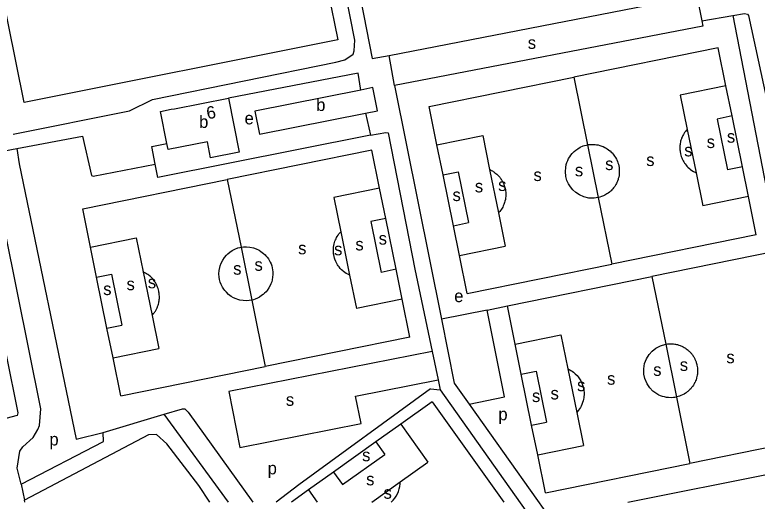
# Model space of a CAD drawing. Extents: x 160204 to 161526, y 379528 to 381793.
# Drawn here: x 160863 to 161102.1, y 380224.6 to 380381.3 of the extents above; entities that cross this region are included whole.
import ezdxf

# ---------------------------------------------------------------- set-up
doc = ezdxf.new("R2010")
doc.units = 0
for name, color, linetype in [('BLT_Basislijn', 7, 'Continuous'), ('BLT_Bebouwing', 7, 'Continuous'), ('BLT_Centroide', 7, 'Continuous'), ('BLT_Huisnummer', 7, 'Continuous')]:
    doc.layers.add(name, color=color, linetype=linetype)

msp = doc.modelspace()

# ---------------------------------------------------------------- linework, layer by layer
at = {"layer": 'BLT_Basislijn'}
for p, q in [((161084.23, 380379.36), (161094.28, 380381.12)), ((161094.28, 380381.12), (161108.89, 380305.3)), ((161089.54, 380370.73), (161042.99, 380361.26)), ((161092.04, 380358.42), (161089.54, 380370.73)), ((160985.22, 380358.5), (160983.57, 380368.26)), ((160996.44, 380351.79), (161042.99, 380361.26)), ((161042.99, 380361.26), (161047.43, 380339.43)), ((160985.22, 380358.5), (161000.38, 380283.25)), ((161092.04, 380358.42), (161077.31, 380355.42)), ((161094.02, 380348.73), (161092.04, 380358.42)), ((161077.31, 380355.42), (161079.55, 380344.42)), ((160998.94, 380339.48), (160996.44, 380351.79)), ((160975.88, 380349.59), (160977.58, 380342.53)), ((161094.02, 380348.73), (161089.2, 380347.75)), ((161097.35, 380332.34), (161094.02, 380348.73)), ((161089.2, 380347.75), (161092.54, 380331.36)), ((161079.55, 380344.42), (161082.4, 380330.42)), ((160998.94, 380339.48), (161013.68, 380342.48)), ((161013.68, 380342.48), (161015.91, 380331.48)), ((161000.92, 380329.78), (160998.94, 380339.48)), ((161047.43, 380339.43), (161050.89, 380322.43)), ((160977.95, 380337.73), (160931.4, 380328.25)), ((160980.46, 380325.42), (160977.95, 380337.73)), ((161097.35, 380332.34), (161092.54, 380331.36)), ((161099.31, 380322.74), (161097.35, 380332.34)), ((161000.92, 380329.78), (161005.73, 380330.76)), ((161004.25, 380313.39), (161000.92, 380329.78)), ((161005.73, 380330.76), (161009.07, 380314.37)), ((161015.91, 380331.48), (161018.76, 380317.48)), ((161082.4, 380330.42), (161084.57, 380319.74)), ((160884.85, 380318.78), (160931.4, 380328.25)), ((160931.4, 380328.25), (160935.83, 380306.46)), ((160980.46, 380325.42), (160965.72, 380322.42)), ((160982.43, 380315.72), (160980.46, 380325.42)), ((160965.72, 380322.42), (160967.96, 380311.42)), ((161050.89, 380322.43), (161055.25, 380301.01)), ((161099.31, 380322.74), (161084.57, 380319.74)), ((161101.8, 380310.49), (161099.31, 380322.74)), ((160887.35, 380306.47), (160884.85, 380318.78)), ((161018.76, 380317.48), (161020.94, 380306.79)), ((160982.43, 380315.72), (160977.61, 380314.74)), ((160985.76, 380299.33), (160982.43, 380315.72)), ((160977.61, 380314.74), (160980.95, 380298.35)), ((161004.25, 380313.39), (161009.07, 380314.37)), ((161006.21, 380303.79), (161004.25, 380313.39)), ((160967.96, 380311.42), (160970.8, 380297.45)), ((161101.8, 380310.49), (161055.25, 380301.01)), ((160887.35, 380306.47), (160902.09, 380309.47)), ((160902.09, 380309.47), (160904.31, 380298.53)), ((160889.33, 380296.78), (160887.35, 380306.47)), ((160932.24, 380304.88), (160933, 380305.39)), ((160933, 380305.39), (160933.89, 380305.85)), ((160933.89, 380305.85), (160934.84, 380306.2)), ((160934.84, 380306.2), (160935.52, 380306.37)), ((160935.52, 380306.37), (160935.83, 380306.46)), ((160935.83, 380306.46), (160936.65, 380306.55)), ((160935.83, 380306.46), (160939.3, 380289.41)), ((160936.04, 380306.48), (160936.13, 380306.49)), ((160936.65, 380306.55), (160937.61, 380306.58)), ((160937.61, 380306.58), (160938.71, 380306.49)), ((160938.71, 380306.49), (160939.84, 380306.24)), ((160939.84, 380306.24), (160940.7, 380305.95)), ((160940.7, 380305.95), (160941.73, 380305.45)), ((160941.73, 380305.45), (160942.26, 380305.11)), ((161006.21, 380303.79), (161020.94, 380306.79)), ((161108.89, 380305.3), (161068.19, 380297.01)), ((160929.94, 380302.31), (160930.48, 380303.1)), ((160930.48, 380303.1), (160931.12, 380303.87)), ((160931.12, 380303.87), (160931.6, 380304.35)), ((160931.6, 380304.35), (160932.24, 380304.88)), ((160942.26, 380305.11), (160943.13, 380304.45)), ((160943.13, 380304.45), (160943.58, 380304.01)), ((160943.58, 380304.01), (160943.87, 380303.71)), ((160943.87, 380303.71), (160944.27, 380303.24)), ((160944.27, 380303.24), (160944.64, 380302.72)), ((161008.7, 380291.54), (161006.21, 380303.79)), ((160929.11, 380300.4), (160929.43, 380301.31)), ((160929.43, 380301.31), (160929.94, 380302.31)), ((160944.64, 380302.72), (160944.93, 380302.24)), ((160944.93, 380302.24), (160945.24, 380301.66)), ((160945.24, 380301.66), (160945.51, 380301.06)), ((160945.51, 380301.06), (160945.71, 380300.48)), ((161008.7, 380291.54), (161055.25, 380301.01)), ((160904.31, 380298.53), (160907.17, 380284.48)), ((160928.73, 380297.84), (160928.81, 380298.98)), ((160928.81, 380298.98), (160928.96, 380299.89)), ((160928.96, 380299.89), (160929.11, 380300.4)), ((160945.71, 380300.48), (160945.9, 380299.77)), ((160945.9, 380299.77), (160946.02, 380299.11)), ((160946.02, 380299.11), (160946.08, 380298.52)), ((160946.08, 380298.52), (160946.1, 380297.63)), ((160985.76, 380299.33), (160980.95, 380298.35)), ((160987.72, 380289.73), (160985.76, 380299.33)), ((160889.33, 380296.78), (160894.14, 380297.76)), ((160892.66, 380280.39), (160889.33, 380296.78)), ((160894.14, 380297.76), (160897.48, 380281.37)), ((160928.8, 380296.79), (160928.73, 380297.84)), ((160928.93, 380296.06), (160928.8, 380296.79)), ((160929.17, 380295.2), (160928.93, 380296.06)), ((160945.88, 380295.95), (160945.72, 380295.35)), ((160946.02, 380296.76), (160945.88, 380295.95)), ((160946.1, 380297.63), (160946.02, 380296.76)), ((160970.8, 380297.45), (160972.98, 380286.73)), ((161021.64, 380287.54), (161068.19, 380297.01)), ((161068.19, 380297.01), (161072.63, 380275.19)), ((160929.48, 380294.39), (160929.17, 380295.2)), ((160929.89, 380293.59), (160929.48, 380294.39)), ((160930.27, 380292.96), (160929.89, 380293.59)), ((160944.81, 380293.34), (160944.24, 380292.51)), ((160945.22, 380294.08), (160944.81, 380293.34)), ((160945.48, 380294.64), (160945.22, 380294.08)), ((160945.72, 380295.35), (160945.48, 380294.64)), ((160930.62, 380292.5), (160930.27, 380292.96)), ((160931.13, 380291.93), (160930.62, 380292.5)), ((160931.84, 380291.23), (160931.13, 380291.93)), ((160932.67, 380290.62), (160931.84, 380291.23)), ((160943, 380291.24), (160942.48, 380290.85)), ((160943.44, 380291.66), (160943, 380291.24)), ((160943.9, 380292.11), (160943.44, 380291.66)), ((160944.24, 380292.51), (160943.9, 380292.11)), ((160933.45, 380290.18), (160932.67, 380290.62)), ((160934.24, 380289.82), (160933.45, 380290.18)), ((160934.83, 380289.61), (160934.24, 380289.82)), ((160935.5, 380289.42), (160934.83, 380289.61)), ((160936.49, 380289.24), (160935.5, 380289.42)), ((160937.46, 380289.21), (160936.49, 380289.24)), ((160938.42, 380289.27), (160937.46, 380289.21)), ((160939.3, 380289.41), (160938.42, 380289.27)), ((160939.82, 380289.55), (160939.3, 380289.41)), ((160939.3, 380289.41), (160943.66, 380268.01)), ((160940.43, 380289.76), (160939.82, 380289.55)), ((160941.09, 380290.03), (160940.43, 380289.76)), ((160941.74, 380290.37), (160941.09, 380290.03)), ((160942.48, 380290.85), (160941.74, 380290.37)), ((160987.72, 380289.73), (160972.98, 380286.73)), ((160990.21, 380277.48), (160987.72, 380289.73)), ((161015.11, 380286.22), (161000.38, 380283.25)), ((161015.11, 380286.22), (161021.64, 380287.54)), ((161024.14, 380275.23), (161021.64, 380287.54)), ((160907.17, 380284.48), (160909.35, 380273.78)), ((160892.66, 380280.39), (160897.48, 380281.37)), ((161000.38, 380283.25), (161004.52, 380262.7)), ((160894.62, 380270.78), (160892.66, 380280.39)), ((160990.21, 380277.48), (160943.66, 380268.01)), ((161024.14, 380275.23), (161038.88, 380278.23)), ((161038.88, 380278.23), (161041.12, 380267.24)), ((161026.12, 380265.54), (161024.14, 380275.23)), ((161072.63, 380275.19), (161076.09, 380258.18)), ((160894.62, 380270.78), (160909.35, 380273.78)), ((160897.11, 380258.54), (160894.62, 380270.78)), ((160897.11, 380258.54), (160943.66, 380268.01)), ((161041.12, 380267.24), (161043.96, 380253.24)), ((161026.12, 380265.54), (161030.93, 380266.52)), ((161029.45, 380249.15), (161026.12, 380265.54)), ((161030.93, 380266.52), (161034.27, 380250.13)), ((161004.52, 380262.7), (161009.34, 380255.9)), ((160996.92, 380260.88), (160999.97, 380260.47)), ((160999.97, 380260.47), (161053.56, 380184.93)), ((161076.09, 380258.18), (161080.45, 380236.77)), ((160997.43, 380256.65), (160987.26, 380249.4)), ((160997.43, 380256.65), (161020.47, 380224.32)), ((161009.34, 380255.9), (161057.78, 380187.62)), ((160891.4, 380246.76), (160911.04, 380252.7)), ((160931.83, 380224.32), (160911.04, 380252.7)), ((161043.96, 380253.24), (161046.14, 380242.54)), ((160987.26, 380249.4), (160979.27, 380243.71)), ((160987.26, 380249.4), (160995.98, 380237.15)), ((161029.45, 380249.15), (161034.27, 380250.13)), ((161031.41, 380239.55), (161029.45, 380249.15)), ((161127, 380246.24), (161080.45, 380236.77)), ((160979.27, 380243.71), (160965.65, 380234)), ((160979.27, 380243.71), (160982.13, 380239.71)), ((161031.41, 380239.55), (161046.14, 380242.54)), ((160968.51, 380230), (160982.13, 380239.71)), ((161033.9, 380227.3), (161031.41, 380239.55)), ((161060.45, 380224.32), (161136.14, 380239.36)), ((160987.1, 380230.82), (160995.98, 380237.15)), ((161033.9, 380227.3), (161080.45, 380236.77)), ((160965.65, 380234), (160957.6, 380228.26)), ((160965.65, 380234), (160968.51, 380230)), ((160865.02, 380230.15), (160866.11, 380224.96)), ((160977.98, 380224.32), (160987.1, 380230.82)), ((160957.6, 380228.26), (160952.08, 380224.32)), ((160957.6, 380228.26), (160960.4, 380224.32)), ((160866.24, 380224.32), (160866.11, 380224.96))]:
    msp.add_line(p, q, dxfattribs=at)
for points in [[(160862.4, 380342.89), (160899.88, 380350.43), (160907.33, 380354.09), (160966.36, 380366.04), (160969.23, 380366.8), (160971.97, 380368.63), (160972.33, 380369.68), (160972.48, 380373.18), (160947.15, 380501.94), (160947.23, 380502.7), (160955.13, 380504.39), (160952.23, 380519.45)], [(160961.41, 380463.33), (160959.6, 380462.97), (160960.64, 380456.41), (160978.09, 380367.21)], [(160855.42, 380404.86), (160853.74, 380413.3), (160853.25, 380417.58), (160953.85, 380437.27), (160960.59, 380405.79), (160960.75, 380403.91), (160967.05, 380373.22), (160866.02, 380353.12), (160855.42, 380404.86)], [(161079.12, 380386.74), (161082.68, 380387.43), (161084.23, 380379.36)], [(160983.57, 380368.26), (161074.21, 380385.79)], [(161094.28, 380381.12), (161098, 380381.77), (161099.02, 380381.54), (161099.3, 380381.07), (161112.98, 380318.06), (161113.11, 380317.77), (161120.31, 380318.94), (161121.12, 380317.68), (161126.85, 380288.91), (161136.14, 380239.36)], [(161084.23, 380379.36), (161084.56, 380377.64), (160985.22, 380358.5)], [(160978.09, 380367.21), (160983.57, 380368.26)], [(160974.39, 380357.08), (160973.55, 380362.55), (160931.8, 380354.52)], [(161079.55, 380344.42), (161079.5, 380344.38), (161079.34, 380344.2), (161079.17, 380344), (161078.96, 380343.73), (161078.71, 380343.39), (161078.48, 380343.02), (161078.33, 380342.76), (161078.16, 380342.47), (161078.05, 380342.23), (161077.91, 380341.95), (161077.77, 380341.6), (161077.67, 380341.33), (161077.55, 380340.94), (161077.45, 380340.58), (161077.37, 380340.24), (161077.31, 380339.89), (161077.25, 380339.51), (161077.22, 380339.2), (161077.19, 380338.91), (161077.19, 380338.66), (161077.18, 380338.23), (161077.21, 380337.81), (161077.24, 380337.46), (161077.28, 380337.14), (161077.36, 380336.69), (161077.4, 380336.51), (161077.5, 380336.12), (161077.62, 380335.71), (161077.69, 380335.51), (161077.78, 380335.25), (161077.91, 380334.96), (161078.12, 380334.51), (161078.24, 380334.29), (161078.43, 380333.94), (161078.68, 380333.54), (161078.88, 380333.26), (161079.17, 380332.89), (161079.49, 380332.52), (161079.74, 380332.26), (161080.38, 380331.68), (161080.67, 380331.45), (161081.06, 380331.17), (161081.57, 380330.85), (161082.07, 380330.59), (161082.4, 380330.42)], [(160863.57, 380338.29), (160884.75, 380342.19), (160887.72, 380329.58), (160888.26, 380329.29), (160908.2, 380333.23)], [(160977.58, 380342.53), (160909.05, 380328.91), (160908.2, 380333.23)], [(160977.58, 380342.53), (160982.5, 380343.43), (160983.2, 380343.31), (160991.86, 380299.42), (160997.4, 380272.83)], [(160908.2, 380333.23), (160907.07, 380338.9), (160911.95, 380339.89)], [(161050.89, 380322.43), (161049.64, 380322.24), (161047.82, 380322.3), (161046.21, 380322.69), (161044.84, 380323.29), (161043.68, 380324.05), (161042.72, 380324.92), (161041.93, 380325.88), (161041.34, 380326.83), (161040.83, 380327.99), (161040.49, 380329.26), (161040.33, 380330.83), (161040.41, 380332.09), (161040.6, 380333.05), (161040.8, 380333.73), (161041.07, 380334.4), (161041.34, 380334.98), (161041.7, 380335.59), (161042.09, 380336.14), (161042.52, 380336.67), (161043.1, 380337.26), (161043.63, 380337.71), (161044.3, 380338.19), (161045.13, 380338.67), (161046.04, 380339.06)], [(161046.04, 380339.06), (161046.49, 380339.21), (161047.08, 380339.36), (161047.43, 380339.43)], [(161047.43, 380339.43), (161047.8, 380339.5), (161048.19, 380339.55), (161048.73, 380339.58), (161049.29, 380339.58), (161049.95, 380339.53), (161050.33, 380339.48), (161050.86, 380339.39), (161051.41, 380339.25), (161052.01, 380339.05), (161052.5, 380338.85), (161052.98, 380338.62), (161053.5, 380338.34), (161053.8, 380338.14), (161054.24, 380337.84), (161054.59, 380337.55), (161054.71, 380337.46), (161055.09, 380337.1), (161055.37, 380336.81), (161055.69, 380336.44), (161055.96, 380336.1), (161056.19, 380335.78), (161056.44, 380335.4), (161056.75, 380334.83), (161056.88, 380334.57), (161057.09, 380334.07), (161057.26, 380333.62), (161057.38, 380333.21), (161057.51, 380332.69), (161057.6, 380332.17), (161057.65, 380331.79), (161057.67, 380331.46), (161057.69, 380330.94), (161057.68, 380330.45), (161057.65, 380330.09), (161057.59, 380329.56), (161057.49, 380329.04), (161057.37, 380328.55), (161057.29, 380328.28), (161057.1, 380327.74), (161056.92, 380327.31), (161056.77, 380327.02), (161056.58, 380326.64), (161056.33, 380326.24), (161056.2, 380326.04), (161056.04, 380325.81), (161055.83, 380325.53), (161055.58, 380325.23), (161055.29, 380324.91), (161055.03, 380324.64), (161054.88, 380324.5), (161054.49, 380324.17), (161054.11, 380323.87), (161053.72, 380323.61), (161053.38, 380323.4), (161053.06, 380323.22), (161052.55, 380322.97), (161052, 380322.75), (161051.39, 380322.55), (161051.03, 380322.46), (161050.89, 380322.43)], [(160865.02, 380230.15), (160863.73, 380235.26), (160864.58, 380240.74), (160865.6, 380242.18), (160868.88, 380245.17), (160870.37, 380247.71), (160870.95, 380249.02), (160871.35, 380254.34), (160855.97, 380330.15), (160855.04, 380336.66), (160863.57, 380338.29)], [(160863.57, 380338.29), (160864.37, 380333.36), (160882.69, 380244.66), (160891.4, 380246.76)], [(160860.23, 380271.76), (160863.94, 380253.07), (160863.75, 380252.24), (160860.12, 380251.32), (160859.76, 380251.99), (160843.87, 380330.48), (160843.89, 380332.62), (160846.26, 380333.83), (160847.2, 380333.94), (160848.49, 380329.53), (160860.23, 380271.76)], [(161015.91, 380331.48), (161016.18, 380331.35), (161016.46, 380331.21), (161016.82, 380331.01), (161017.01, 380330.89), (161017.3, 380330.71), (161017.64, 380330.46), (161017.93, 380330.23), (161018.23, 380329.98), (161018.43, 380329.8), (161018.64, 380329.59), (161018.87, 380329.34), (161019.05, 380329.14), (161019.19, 380328.97), (161019.35, 380328.75), (161019.49, 380328.56), (161019.67, 380328.3), (161019.83, 380328.05), (161019.98, 380327.8), (161020.07, 380327.64), (161020.18, 380327.43), (161020.34, 380327.09), (161020.52, 380326.68), (161020.65, 380326.3), (161020.75, 380326.01), (161020.84, 380325.66), (161020.91, 380325.41), (161021, 380324.99), (161021.05, 380324.61), (161021.1, 380324.16), (161021.13, 380323.59), (161021.12, 380323.21), (161021.1, 380322.78), (161021.06, 380322.36), (161020.98, 380321.87), (161020.86, 380321.33), (161020.71, 380320.81), (161020.52, 380320.25), (161020.29, 380319.73), (161020.12, 380319.39), (161019.9, 380318.99), (161019.69, 380318.67), (161019.46, 380318.33), (161019.17, 380317.95), (161018.76, 380317.48)], [(160970.8, 380297.45), (160970.65, 380297.5), (160970.19, 380297.73), (160969.72, 380298.01), (160969.28, 380298.3), (160968.87, 380298.61), (160968.64, 380298.79), (160968.23, 380299.18), (160967.79, 380299.64), (160967.41, 380300.09), (160967.12, 380300.49), (160966.96, 380300.74), (160966.66, 380301.25), (160966.37, 380301.83), (160966.08, 380302.55), (160965.98, 380302.88), (160965.83, 380303.43), (160965.73, 380303.95), (160965.65, 380304.37), (160965.63, 380304.73), (160965.6, 380305.39), (160965.62, 380306.03), (160965.66, 380306.49), (160965.74, 380307.03), (160965.85, 380307.54), (160965.98, 380308.02), (160966.1, 380308.37), (160966.27, 380308.79), (160966.43, 380309.16), (160966.62, 380309.56), (160966.82, 380309.9), (160967.09, 380310.34), (160967.38, 380310.75), (160967.68, 380311.12), (160967.96, 380311.42)], [(160907.17, 380284.48), (160907.29, 380284.61), (160907.46, 380284.8), (160907.66, 380285.05), (160907.92, 380285.38), (160908.09, 380285.63), (160908.25, 380285.9), (160908.47, 380286.28), (160908.67, 380286.66), (160908.81, 380286.97), (160908.91, 380287.21), (160908.97, 380287.37), (160909.11, 380287.76), (160909.23, 380288.14), (160909.32, 380288.52), (160909.4, 380288.89), (160909.45, 380289.17), (160909.49, 380289.56), (160909.53, 380289.97), (160909.54, 380290.29), (160909.53, 380290.71), (160909.52, 380291.07), (160909.49, 380291.36), (160909.46, 380291.63), (160909.41, 380291.96), (160909.34, 380292.33), (160909.26, 380292.68), (160909.12, 380293.14), (160908.98, 380293.54), (160908.84, 380293.9), (160908.73, 380294.14), (160908.56, 380294.48), (160908.38, 380294.82), (160908.26, 380295.03), (160908.07, 380295.32), (160907.83, 380295.67), (160907.54, 380296.04), (160907.28, 380296.33), (160906.97, 380296.66), (160906.64, 380296.98), (160906.32, 380297.25), (160906.12, 380297.4), (160905.84, 380297.61), (160905.44, 380297.88), (160905.06, 380298.11), (160904.63, 380298.33), (160904.39, 380298.44), (160904.25, 380298.51)], [(161009.34, 380255.9), (161020.66, 380258.21), (161015.11, 380286.22)], [(161076.09, 380258.18), (161075.53, 380258.08), (161075.1, 380258.02), (161074.37, 380257.98), (161073.51, 380258.01), (161072.84, 380258.08), (161072.24, 380258.2), (161071.55, 380258.39), (161070.92, 380258.62), (161070.47, 380258.82), (161069.76, 380259.2), (161069.15, 380259.61), (161068.53, 380260.09), (161067.49, 380261.16), (161066.63, 380262.43), (161065.9, 380264.13), (161065.6, 380265.53), (161065.55, 380267.23), (161065.84, 380268.96), (161066.4, 380270.45), (161067.27, 380271.88), (161068.29, 380273), (161069.44, 380273.91), (161070.99, 380274.72), (161072.63, 380275.19)], [(161072.63, 380275.19), (161073.16, 380275.27)], [(161073.16, 380275.27), (161073.35, 380275.29), (161073.63, 380275.32), (161073.82, 380275.33), (161074.18, 380275.34), (161074.53, 380275.33), (161074.9, 380275.31), (161075.18, 380275.28), (161075.52, 380275.24), (161075.76, 380275.2), (161076.08, 380275.14), (161076.4, 380275.06), (161076.6, 380275), (161076.89, 380274.91), (161077.25, 380274.79), (161077.52, 380274.68), (161077.84, 380274.55), (161078.05, 380274.44), (161078.3, 380274.32), (161078.56, 380274.17), (161078.81, 380274.02), (161079.01, 380273.89), (161079.27, 380273.71), (161079.59, 380273.48), (161079.87, 380273.24), (161080.01, 380273.12), (161080.18, 380272.96), (161080.35, 380272.79), (161080.52, 380272.62), (161080.68, 380272.44), (161080.77, 380272.34), (161080.93, 380272.16), (161081.08, 380271.97), (161081.21, 380271.78), (161081.34, 380271.61), (161081.44, 380271.47), (161081.53, 380271.33), (161081.66, 380271.12), (161081.78, 380270.91), (161081.9, 380270.69), (161081.99, 380270.52), (161082.05, 380270.37), (161082.15, 380270.17), (161082.24, 380269.96), (161082.32, 380269.76), (161082.39, 380269.56), (161082.49, 380269.26), (161082.59, 380268.95), (161082.65, 380268.68), (161082.71, 380268.46), (161082.78, 380268), (161082.84, 380267.6), (161082.88, 380267.18), (161082.89, 380266.72), (161082.89, 380266.34), (161082.86, 380265.98), (161082.83, 380265.6), (161082.78, 380265.25), (161082.71, 380264.85), (161082.6, 380264.42), (161082.51, 380264.11), (161082.39, 380263.72), (161082.24, 380263.36), (161082.09, 380263), (161081.96, 380262.74), (161081.78, 380262.39), (161081.55, 380262.01), (161081.34, 380261.7), (161081.1, 380261.37), (161080.98, 380261.22), (161080.68, 380260.86), (161080.41, 380260.58), (161080.07, 380260.24), (161079.74, 380259.96), (161079.59, 380259.84), (161079.25, 380259.59), (161078.97, 380259.4), (161078.6, 380259.16), (161078, 380258.84), (161077.52, 380258.63), (161077.1, 380258.47), (161076.61, 380258.31), (161076.22, 380258.21), (161076.09, 380258.18)], [(160997.4, 380272.83), (160931.88, 380259.92), (160935.42, 380241.95), (160974.5, 380249.63), (160972.75, 380258.47), (160999.29, 380263.71)], [(160997.4, 380272.83), (160999.29, 380263.71)], [(161041.12, 380267.24), (161041.57, 380267.02), (161042.09, 380266.73), (161042.48, 380266.48), (161042.92, 380266.16), (161043.51, 380265.66), (161044.07, 380265.09), (161044.45, 380264.65), (161044.85, 380264.1), (161045.27, 380263.4), (161045.65, 380262.64), (161045.95, 380261.8), (161046.15, 380261), (161046.28, 380260.14), (161046.32, 380259.73), (161046.33, 380258.99), (161046.28, 380258.3), (161046.23, 380257.92), (161046.15, 380257.45), (161046.03, 380256.97), (161045.87, 380256.41), (161045.63, 380255.79), (161045.37, 380255.23), (161045.16, 380254.86), (161044.87, 380254.38), (161044.53, 380253.91), (161044.21, 380253.52), (161043.96, 380253.24)], [(160999.29, 380263.71), (160999.97, 380260.47)], [(160996.92, 380260.88), (160954.42, 380229.9), (160947.16, 380224.32)], [(160911.04, 380252.7), (160916.99, 380254.43), (160917.69, 380254.34), (160918.83, 380253.33), (160939.63, 380224.32)], [(160865.02, 380230.15), (160891.5, 380243.83), (160891.4, 380246.76)], [(160925.74, 380224.32), (160922.26, 380229.65), (160911.89, 380243.12), (160908.64, 380246.11), (160906.06, 380245.97), (160866.11, 380224.96)], [(160984.23, 380224.32), (160984.82, 380224.92), (160985.35, 380225.56), (160985.82, 380226.25), (160986.22, 380226.99), (160986.55, 380227.76), (160986.8, 380228.56), (160986.98, 380229.38), (160987.07, 380230.21), (160987.1, 380230.82)]]:
    msp.add_lwpolyline(points, dxfattribs=at)
at = {"layer": 'BLT_Bebouwing'}
for points in [[(160974.39, 380357.08), (160940.29, 380350.33), (160941.77, 380342.83), (160975.88, 380349.59)], [(160975.88, 380349.59), (160979.79, 380350.36), (160978.3, 380357.86), (160974.39, 380357.08)], [(160911.95, 380339.89), (160909.9, 380350.21), (160913.3, 380350.88), (160914.39, 380351.07), (160931.8, 380354.52)], [(160931.8, 380354.52), (160935.26, 380337.05), (160926.01, 380335.22)], [(160926.01, 380335.22), (160924.99, 380340.41), (160912.34, 380337.9), (160911.95, 380339.89)]]:
    msp.add_lwpolyline(points, dxfattribs=at)

# ---------------------------------------------------------------- texts
at = {"layer": 'BLT_Centroide'}
for s, p in [('s', (161028.19, 380370.34)), ('b', (160960.04, 380350.34)), ('b', (160922.33, 380344.88)), ('e', (160936.98, 380346.02)), ('s', (161085.83, 380338.4)), ('s', (161092.35, 380340.12)), ('s', (161078.6, 380335.71)), ('s', (161053.13, 380331.3)), ('s', (161066.36, 380332.61)), ('s', (161043.39, 380329.29)), ('s', (161030.04, 380327.77)), ('s', (161011.16, 380324.11)), ('s', (161018.66, 380324.57)), ('s', (161003.96, 380321.32)), ('s', (160980.17, 380307.29)), ('s', (160972.67, 380305.41)), ('s', (160954.24, 380304.16)), ('s', (160965.8, 380303.85)), ('s', (160933.31, 380297.6)), ('s', (160940.18, 380298.85)), ('s', (160898.95, 380292.6)), ('s', (160905.82, 380293.22)), ('s', (160891.45, 380291.03)), ('e', (161004.51, 380288.76)), ('s', (161092.16, 380269.07)), ('s', (161077.17, 380266.6)), ('s', (161068.61, 380264.99)), ('s', (161053.75, 380262.15)), ('s', (161044.07, 380260.06)), ('s', (161035.54, 380257.4)), ('s', (160950.28, 380255.35)), ('s', (161029.56, 380256.57)), ('p', (161018.73, 380250.7)), ('p', (160874.11, 380242.58)), ('s', (160974.84, 380237.5)), ('p', (160944.41, 380233.27)), ('s', (160976.14, 380229.73)), ('s', (160981.75, 380225.41))]:
    msp.add_text(s, height=4, dxfattribs=at).set_placement(p)
at = {"layer": 'BLT_Huisnummer'}
msp.add_text('6', height=4, rotation=10.3267, dxfattribs=at).set_placement((160925.07, 380347.63))

doc.saveas('drawing.dxf')
